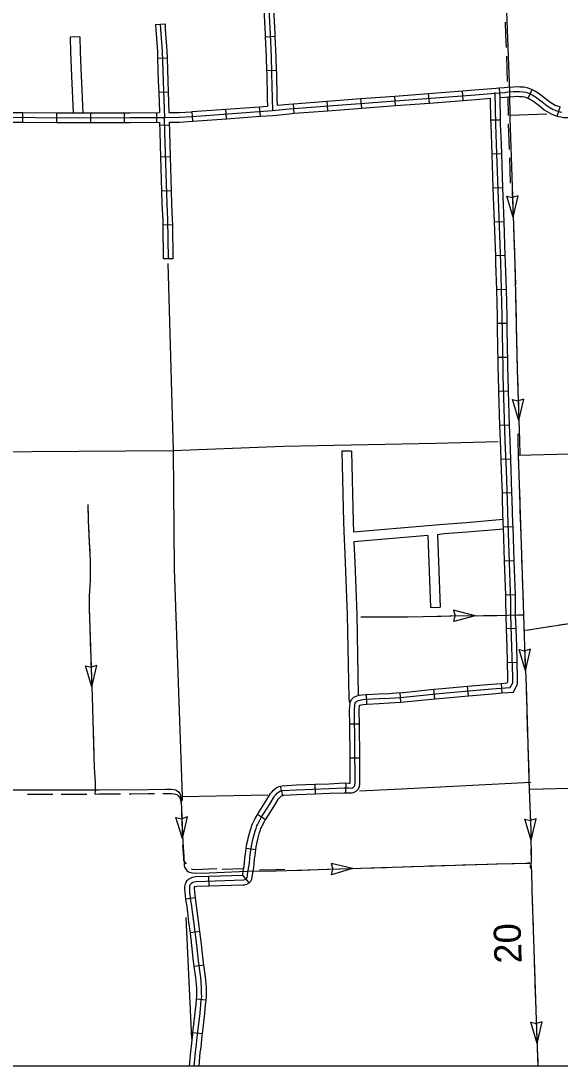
# Model space of a CAD drawing. Extents: x 1164457 to 1439835, y 1590918 to 1773502.
# Drawn here: x 1322808 to 1331207, y 1614471 to 1630737 of the extents above; entities that cross this region are included whole.
import ezdxf

# ---------------------------------------------------------------- set-up
doc = ezdxf.new("R2010")
doc.units = 0
for name, color, linetype in [('Level 32', 7, 'Continuous'), ('Level 43', 7, 'Continuous'), ('Level 46', 7, 'Continuous'), ('Level 5', 7, 'Continuous'), ('R_Draft', 7, 'Continuous')]:
    doc.layers.add(name, color=color, linetype=linetype)

msp = doc.modelspace()

# ---------------------------------------------------------------- linework, layer by layer
at = {"layer": 'Level 32'}
for p, q in [((1324905, 1630683), (1325055, 1630689)), ((1326615, 1630490), (1326765, 1630497)), ((1324938, 1630157), (1325088, 1630162)), ((1326636, 1629964), (1326786, 1629968)), ((1324955, 1629629), (1325104, 1629634)), ((1328644, 1629419), (1328633, 1629568)), ((1329171, 1629459), (1329159, 1629609)), ((1329697, 1629499), (1329686, 1629649)), ((1330272, 1629544), (1330261, 1629693)), ((1330708, 1629534), (1330771, 1629670)), ((1326539, 1629253), (1326527, 1629402)), ((1327065, 1629299), (1327053, 1629448)), ((1327591, 1629339), (1327580, 1629488)), ((1328118, 1629379), (1328106, 1629528)), ((1331164, 1629256), (1331207, 1629400)), ((1322840, 1629160), (1322841, 1629310)), ((1323368, 1629157), (1323369, 1629307)), ((1323896, 1629156), (1323896, 1629306)), ((1324424, 1629157), (1324424, 1629307)), ((1324927, 1629159), (1324926, 1629309)), ((1325485, 1629175), (1325474, 1629325)), ((1326012, 1629214), (1326001, 1629363)), ((1325123, 1629114), (1324974, 1629107)), ((1330280, 1629194), (1330130, 1629191)), ((1325140, 1628619), (1324990, 1628614)), ((1330298, 1628668), (1330148, 1628662)), ((1325155, 1628091), (1325005, 1628087)), ((1330316, 1628140), (1330166, 1628135)), ((1330335, 1627612), (1330185, 1627607)), ((1325173, 1627562), (1325023, 1627560)), ((1325181, 1627034), (1325031, 1627032)), ((1330354, 1627085), (1330204, 1627079)), ((1330370, 1626556), (1330220, 1626552)), ((1330384, 1626027), (1330234, 1626026)), ((1330391, 1625500), (1330241, 1625497)), ((1330404, 1624973), (1330254, 1624968)), ((1330420, 1624445), (1330270, 1624441)), ((1330438, 1623918), (1330288, 1623912)), ((1330458, 1623390), (1330308, 1623385)), ((1330475, 1622862), (1330325, 1622857)), ((1330492, 1622335), (1330342, 1622330)), ((1330510, 1621807), (1330360, 1621802)), ((1330523, 1621280), (1330373, 1621274)), ((1330539, 1620751), (1330389, 1620747)), ((1328727, 1620133), (1328718, 1620283)), ((1329255, 1620186), (1329240, 1620336)), ((1329780, 1620233), (1329767, 1620383)), ((1330306, 1620278), (1330294, 1620427)), ((1328199, 1620105), (1328192, 1620255)), ((1328081, 1619792), (1327931, 1619791)), ((1328086, 1619264), (1327936, 1619263)), ((1326886, 1618683), (1326853, 1618829)), ((1327399, 1618708), (1327394, 1618858)), ((1327868, 1618726), (1327875, 1618876)), ((1326619, 1618304), (1326492, 1618384)), ((1326467, 1617835), (1326318, 1617857)), ((1325739, 1617276), (1325735, 1617426)), ((1326363, 1617322), (1326263, 1617442)), ((1325529, 1617087), (1325380, 1617068)), ((1325596, 1616563), (1325448, 1616544)), ((1325658, 1616040), (1325510, 1616019)), ((1325694, 1615497), (1325545, 1615511)), ((1325636, 1614971), (1325487, 1614988))]:
    msp.add_line(p, q, dxfattribs=at)
for points in [[(1326680, 1632040), (1326659, 1632033), (1326642, 1632021), (1326631, 1632008), (1326618, 1631991), (1326611, 1631974), (1326606, 1631955), (1326603, 1631927), (1326605, 1631875), (1326612, 1631805), (1326623, 1631721), (1326639, 1631515), (1326689, 1630530), (1326705, 1630176), (1326713, 1629923), (1326721, 1629528), (1326728, 1629342)], [(1326589, 1631017), (1326614, 1630526), (1326615, 1630490)], [(1326739, 1631025), (1326763, 1630534), (1326765, 1630497)], [(1324905, 1630683), (1324908, 1630599), (1324935, 1630263), (1324938, 1630157)], [(1324980, 1630686), (1324983, 1630604), (1325010, 1630267), (1325024, 1629795), (1325043, 1629234)], [(1325055, 1630689), (1325058, 1630608), (1325084, 1630271), (1325088, 1630162)], [(1326615, 1630490), (1326630, 1630173), (1326636, 1629964)], [(1326765, 1630497), (1326780, 1630179), (1326786, 1629968)], [(1324938, 1630157), (1324949, 1629793), (1324955, 1629629)], [(1325088, 1630162), (1325099, 1629798), (1325104, 1629634)], [(1326636, 1629964), (1326638, 1629921), (1326646, 1629526), (1326650, 1629411)], [(1326786, 1629968), (1326788, 1629925), (1326796, 1629530), (1326800, 1629425)], [(1330212, 1629689), (1330252, 1629693), (1330337, 1629699), (1330384, 1629705), (1330479, 1629712), (1330542, 1629714), (1330581, 1629712), (1330640, 1629709), (1330690, 1629698), (1330746, 1629682), (1330771, 1629670)], [(1324955, 1629629), (1324965, 1629309)], [(1325043, 1629234), (1325275, 1629237), (1325477, 1629250), (1326728, 1629342), (1326987, 1629368), (1329882, 1629588), (1330258, 1629618), (1330345, 1629624), (1330392, 1629631), (1330483, 1629637), (1330541, 1629639), (1330577, 1629637), (1330630, 1629635), (1330672, 1629626), (1330720, 1629611), (1330770, 1629588), (1330826, 1629556), (1330926, 1629478), (1331004, 1629414), (1331099, 1629357), (1331157, 1629337), (1331203, 1629323), (1331234, 1629316)], [(1325104, 1629634), (1325115, 1629310)], [(1328106, 1629528), (1328633, 1629568)], [(1328633, 1629568), (1329159, 1629609)], [(1329159, 1629609), (1329686, 1629649)], [(1329686, 1629649), (1329876, 1629663), (1330212, 1629689)], [(1330387, 1623280), (1330370, 1623742), (1330352, 1624204), (1330321, 1625212), (1330319, 1625333), (1330314, 1625594), (1330307, 1626141), (1330283, 1626971), (1330217, 1628819), (1330206, 1629129), (1330196, 1629622)], [(1330272, 1629544), (1330353, 1629550), (1330400, 1629556), (1330487, 1629562), (1330540, 1629564), (1330573, 1629562), (1330620, 1629560), (1330653, 1629553), (1330693, 1629541), (1330708, 1629534)], [(1330280, 1629194), (1330272, 1629544)], [(1330771, 1629670), (1330805, 1629655), (1330868, 1629618), (1330973, 1629536), (1331047, 1629476), (1331131, 1629426), (1331180, 1629408), (1331207, 1629400)], [(1326001, 1629363), (1326527, 1629402)], [(1326527, 1629402), (1326650, 1629411)], [(1326800, 1629425), (1326981, 1629443), (1327053, 1629448)], [(1327053, 1629448), (1327580, 1629488)], [(1327580, 1629488), (1328106, 1629528)], [(1327591, 1629339), (1328118, 1629379)], [(1328118, 1629379), (1328644, 1629419)], [(1328644, 1629419), (1329171, 1629459)], [(1329171, 1629459), (1329697, 1629499)], [(1329697, 1629499), (1329887, 1629513), (1330123, 1629532)], [(1330130, 1629191), (1330123, 1629532)], [(1330708, 1629534), (1330736, 1629521), (1330784, 1629493), (1330879, 1629419), (1330961, 1629352), (1331067, 1629289), (1331133, 1629266), (1331164, 1629256)], [(1319672, 1629234), (1321015, 1629234), (1322362, 1629237), (1323701, 1629231), (1324513, 1629232), (1325043, 1629234)], [(1322312, 1629312), (1322362, 1629312), (1322841, 1629310)], [(1322841, 1629310), (1323369, 1629307)], [(1323369, 1629307), (1323701, 1629306), (1323896, 1629306)], [(1323896, 1629306), (1324424, 1629307)], [(1324424, 1629307), (1324512, 1629307), (1324965, 1629309)], [(1325106, 1627033), (1325097, 1627644), (1325086, 1627886), (1325053, 1629006), (1325043, 1629234)], [(1325115, 1629310), (1325272, 1629312), (1325472, 1629324), (1325474, 1629325)], [(1325474, 1629325), (1326001, 1629363)], [(1326012, 1629214), (1326539, 1629253)], [(1326539, 1629253), (1326734, 1629267), (1326994, 1629293), (1327065, 1629299)], [(1327065, 1629299), (1327591, 1629339)], [(1331164, 1629256), (1331184, 1629250), (1331221, 1629242), (1331262, 1629236), (1331322, 1629235), (1331469, 1629237), (1331697, 1629237), (1331714, 1629238)], [(1322312, 1629162), (1322362, 1629162), (1322840, 1629160)], [(1322840, 1629160), (1323368, 1629157)], [(1323368, 1629157), (1323701, 1629156), (1323896, 1629156)], [(1323896, 1629156), (1324424, 1629157)], [(1324424, 1629157), (1324513, 1629157), (1324971, 1629159)], [(1324990, 1628614), (1324978, 1629003), (1324971, 1629159)], [(1325121, 1629160), (1325278, 1629162), (1325482, 1629175), (1325485, 1629175)], [(1325140, 1628619), (1325128, 1629009), (1325121, 1629160)], [(1325485, 1629175), (1326012, 1629214)], [(1330148, 1628662), (1330142, 1628816), (1330131, 1629127), (1330130, 1629191)], [(1330298, 1628668), (1330292, 1628821), (1330281, 1629131), (1330280, 1629194)], [(1325005, 1628087), (1324990, 1628614)], [(1325155, 1628091), (1325140, 1628619)], [(1330166, 1628135), (1330148, 1628662)], [(1330316, 1628140), (1330298, 1628668)], [(1325023, 1627560), (1325022, 1627642), (1325011, 1627883), (1325005, 1628087)], [(1325173, 1627562), (1325172, 1627646), (1325161, 1627889), (1325155, 1628091)], [(1330185, 1627607), (1330166, 1628135)], [(1330335, 1627612), (1330316, 1628140)], [(1330204, 1627079), (1330185, 1627607)], [(1330354, 1627085), (1330335, 1627612)], [(1325031, 1627032), (1325023, 1627560)], [(1325181, 1627034), (1325173, 1627562)], [(1330220, 1626552), (1330208, 1626968), (1330204, 1627079)], [(1330370, 1626556), (1330358, 1626973), (1330354, 1627085)], [(1330234, 1626026), (1330232, 1626139), (1330220, 1626552)], [(1330384, 1626027), (1330382, 1626142), (1330370, 1626556)], [(1330241, 1625497), (1330239, 1625593), (1330234, 1626026)], [(1330391, 1625500), (1330389, 1625595), (1330384, 1626027)], [(1330254, 1624968), (1330246, 1625211), (1330244, 1625332), (1330241, 1625497)], [(1330404, 1624973), (1330396, 1625214), (1330394, 1625335), (1330391, 1625500)], [(1330270, 1624441), (1330254, 1624968)], [(1330420, 1624445), (1330404, 1624973)], [(1330288, 1623912), (1330277, 1624201), (1330270, 1624441)], [(1330438, 1623918), (1330427, 1624206), (1330420, 1624445)], [(1330308, 1623385), (1330295, 1623739), (1330288, 1623912)], [(1330458, 1623390), (1330445, 1623745), (1330438, 1623918)], [(1330325, 1622857), (1330323, 1622913), (1330312, 1623278), (1330308, 1623385)], [(1330475, 1622862), (1330473, 1622918), (1330462, 1623283), (1330458, 1623390)], [(1330470, 1620436), (1330469, 1620526), (1330458, 1620997), (1330440, 1621491), (1330438, 1621702), (1330398, 1622915), (1330387, 1623280)], [(1330342, 1622330), (1330325, 1622857)], [(1330492, 1622335), (1330475, 1622862)], [(1330360, 1621802), (1330342, 1622330)], [(1330510, 1621807), (1330492, 1622335)], [(1330373, 1621274), (1330365, 1621489), (1330363, 1621701), (1330360, 1621802)], [(1330523, 1621280), (1330515, 1621493), (1330513, 1621704), (1330510, 1621807)], [(1330389, 1620747), (1330383, 1620995), (1330373, 1621274)], [(1330539, 1620751), (1330533, 1621000), (1330523, 1621280)], [(1330294, 1620427), (1330385, 1620434), (1330395, 1620454), (1330394, 1620525), (1330389, 1620747)], [(1330306, 1620278), (1330479, 1620291), (1330545, 1620418), (1330544, 1620528), (1330539, 1620751)], [(1328183, 1620180), (1328387, 1620190), (1328545, 1620198), (1328723, 1620208), (1329375, 1620274), (1330146, 1620340), (1330432, 1620363), (1330470, 1620436)], [(1328192, 1620255), (1328384, 1620265), (1328541, 1620272), (1328718, 1620283)], [(1328717, 1620282), (1329240, 1620336)], [(1329240, 1620336), (1329368, 1620348), (1329767, 1620383)], [(1329767, 1620383), (1330140, 1620415), (1330294, 1620427)], [(1329780, 1620233), (1330153, 1620265), (1330306, 1620278)], [(1325509, 1614471), (1325529, 1614690), (1325539, 1614770), (1325559, 1614960), (1325599, 1615298), (1325612, 1615425), (1325619, 1615505), (1325625, 1615551), (1325623, 1615616), (1325622, 1615693), (1325609, 1615852), (1325573, 1616110), (1325547, 1616357), (1325500, 1616720), (1325481, 1616877), (1325465, 1616997), (1325458, 1617044), (1325442, 1617177), (1325438, 1617237), (1325438, 1617261), (1325442, 1617285), (1325448, 1617299), (1325455, 1617309), (1325465, 1617318), (1325486, 1617331), (1325505, 1617339), (1325540, 1617345), (1326280, 1617367), (1326298, 1617373), (1326316, 1617382), (1326327, 1617394), (1326333, 1617406), (1326337, 1617426), (1326340, 1617458), (1326361, 1617571), (1326367, 1617631), (1326372, 1617700), (1326381, 1617765), (1326399, 1617895), (1326414, 1617971), (1326425, 1618020), (1326455, 1618127), (1326471, 1618171), (1326477, 1618190), (1326484, 1618211), (1326497, 1618238), (1326523, 1618290), (1326551, 1618338), (1326689, 1618555), (1326760, 1618671), (1326774, 1618688), (1326798, 1618716), (1326825, 1618738), (1326853, 1618753), (1326886, 1618760), (1327103, 1618771), (1327611, 1618791), (1327846, 1618802), (1327921, 1618799), (1327957, 1618797), (1327973, 1618803), (1327989, 1618810), (1328001, 1618822), (1328010, 1618841), (1328014, 1618867), (1328014, 1618902), (1328004, 1620006), (1328010, 1620102), (1328014, 1620119), (1328023, 1620134), (1328038, 1620147), (1328066, 1620161), (1328091, 1620168), (1328135, 1620175), (1328183, 1620180)], [(1327931, 1619791), (1327929, 1620008), (1327935, 1620115), (1327945, 1620147), (1327963, 1620182), (1327997, 1620210), (1328039, 1620231), (1328075, 1620241), (1328125, 1620249), (1328178, 1620255), (1328192, 1620255)], [(1328199, 1620105), (1328391, 1620115), (1328549, 1620123), (1328727, 1620133)], [(1328727, 1620133), (1328729, 1620133), (1329255, 1620186)], [(1329255, 1620186), (1329382, 1620199), (1329780, 1620233)], [(1328081, 1619792), (1328079, 1620004), (1328084, 1620086), (1328093, 1620090), (1328107, 1620094), (1328144, 1620100), (1328189, 1620105), (1328199, 1620105)], [(1327936, 1619263), (1327931, 1619791)], [(1328086, 1619264), (1328081, 1619792)], [(1327921, 1618724), (1327967, 1618722), (1328001, 1618733), (1328032, 1618748), (1328063, 1618778), (1328083, 1618819), (1328089, 1618861), (1328089, 1618902), (1328086, 1619264)], [(1327927, 1618874), (1327939, 1618873), (1327939, 1618902), (1327936, 1619263)], [(1326492, 1618384), (1326625, 1618595), (1326698, 1618713), (1326715, 1618735), (1326746, 1618771), (1326785, 1618801), (1326827, 1618824), (1326853, 1618829)], [(1326853, 1618829), (1326876, 1618835), (1327099, 1618846), (1327394, 1618858)], [(1327394, 1618858), (1327608, 1618866), (1327846, 1618877), (1327924, 1618874), (1327927, 1618874)], [(1326619, 1618304), (1326752, 1618515), (1326822, 1618628), (1326832, 1618641), (1326850, 1618662), (1326866, 1618675), (1326880, 1618682), (1326886, 1618683)], [(1326886, 1618683), (1326897, 1618685), (1327106, 1618696), (1327399, 1618708)], [(1327399, 1618708), (1327614, 1618716), (1327846, 1618726), (1327918, 1618724), (1327921, 1618724)], [(1326318, 1617857), (1326325, 1617907), (1326341, 1617986), (1326352, 1618038), (1326383, 1618150), (1326400, 1618196), (1326406, 1618215), (1326415, 1618240), (1326430, 1618271), (1326457, 1618326), (1326487, 1618377), (1326492, 1618384)], [(1326467, 1617835), (1326473, 1617882), (1326487, 1617956), (1326498, 1618002), (1326526, 1618104), (1326542, 1618147), (1326548, 1618166), (1326554, 1618182), (1326565, 1618205), (1326589, 1618254), (1326615, 1618299), (1326619, 1618304)], [(1326263, 1617442), (1326263, 1617442), (1326266, 1617469), (1326287, 1617582), (1326293, 1617638), (1326298, 1617707), (1326307, 1617776), (1326318, 1617857)], [(1326267, 1617292), (1326292, 1617293), (1326326, 1617303), (1326363, 1617322), (1326388, 1617351), (1326405, 1617381), (1326411, 1617416), (1326414, 1617447), (1326435, 1617560), (1326442, 1617625), (1326447, 1617692), (1326455, 1617755), (1326467, 1617835)], [(1325380, 1617068), (1325367, 1617170), (1325362, 1617234), (1325363, 1617267), (1325370, 1617307), (1325382, 1617335), (1325398, 1617359), (1325419, 1617378), (1325451, 1617398), (1325484, 1617412), (1325532, 1617420), (1325735, 1617426)], [(1325735, 1617426), (1326263, 1617442)], [(1325529, 1617087), (1325517, 1617185), (1325513, 1617239), (1325513, 1617254), (1325514, 1617260), (1325520, 1617264), (1325526, 1617267), (1325547, 1617270), (1325739, 1617276)], [(1325739, 1617276), (1326267, 1617292)], [(1325448, 1616544), (1325426, 1616711), (1325407, 1616867), (1325391, 1616987), (1325384, 1617034), (1325380, 1617068)], [(1325596, 1616563), (1325575, 1616730), (1325556, 1616886), (1325540, 1617008), (1325533, 1617055), (1325529, 1617087)], [(1325510, 1616019), (1325498, 1616101), (1325473, 1616349), (1325448, 1616544)], [(1325658, 1616040), (1325647, 1616119), (1325622, 1616366), (1325596, 1616563)], [(1325545, 1615511), (1325545, 1615513), (1325550, 1615555), (1325548, 1615615), (1325547, 1615689), (1325534, 1615843), (1325510, 1616019)], [(1325694, 1615496), (1325700, 1615548), (1325698, 1615618), (1325697, 1615696), (1325683, 1615860), (1325658, 1616040)], [(1325487, 1614988), (1325524, 1615306), (1325537, 1615433), (1325545, 1615511)], [(1325636, 1614971), (1325674, 1615290), (1325686, 1615418), (1325694, 1615497)], [(1325434, 1614471), (1325454, 1614698), (1325465, 1614779), (1325485, 1614969), (1325487, 1614988)], [(1325585, 1614471), (1325603, 1614682), (1325614, 1614762), (1325634, 1614952), (1325636, 1614971)]]:
    msp.add_lwpolyline(points, dxfattribs=at)
at = {"layer": 'Level 43'}
for p, q in [((1330477, 1627683), (1330377, 1628011)), ((1330377, 1628011), (1330466, 1627990)), ((1330555, 1628017), (1330467, 1627990)), ((1330477, 1627683), (1330555, 1628017)), ((1330564, 1624516), (1330465, 1624844)), ((1330465, 1624844), (1330554, 1624824)), ((1330642, 1624850), (1330555, 1624824)), ((1330564, 1624516), (1330642, 1624850)), ((1330667, 1620623), (1330569, 1620952)), ((1330569, 1620952), (1330658, 1620931)), ((1330746, 1620957), (1330659, 1620931)), ((1330667, 1620623), (1330746, 1620957)), ((1323913, 1620373), (1323813, 1620701)), ((1323813, 1620701), (1323902, 1620681)), ((1323991, 1620707), (1323903, 1620681)), ((1323913, 1620373), (1323991, 1620707)), ((1325326, 1618013), (1325224, 1618340)), ((1325224, 1618340), (1325313, 1618320)), ((1325401, 1618348), (1325314, 1618320)), ((1325326, 1618013), (1325401, 1618348)), ((1330834, 1618320), (1330746, 1618292)), ((1330758, 1617985), (1330834, 1618320)), ((1330758, 1617985), (1330656, 1618313)), ((1330656, 1618313), (1330745, 1618292)), ((1327974, 1617547), (1327640, 1617625)), ((1327640, 1617625), (1327666, 1617537)), ((1327974, 1617547), (1327646, 1617447)), ((1327646, 1617447), (1327666, 1617536)), ((1330849, 1614824), (1330749, 1615153)), ((1330749, 1615152), (1330838, 1615132)), ((1330926, 1615159), (1330839, 1615132)), ((1330849, 1614824), (1330927, 1615159))]:
    msp.add_line(p, q, dxfattribs=at)
for points in [[(1331528, 1637605), (1330434, 1636452), (1330294, 1636286), (1330272, 1636249), (1330252, 1636222), (1330232, 1636178), (1330218, 1636126), (1330206, 1636072), (1330199, 1636026), (1330189, 1635859), (1330225, 1635001), (1330231, 1634903), (1330320, 1632272), (1330417, 1629632), (1330424, 1629223), (1330503, 1626944), (1330539, 1625302), (1330574, 1624205), (1330581, 1623987)], [(1330350, 1630717), (1330357, 1630519)], [(1330357, 1630519), (1330365, 1630321)], [(1330370, 1630189), (1330384, 1629794)], [(1330391, 1629556), (1330396, 1629266)], [(1330400, 1629134), (1330413, 1628738)], [(1330418, 1628606), (1330432, 1628210)], [(1330463, 1628078), (1330477, 1627683)], [(1330482, 1627551), (1330489, 1627353)], [(1330489, 1627353), (1330496, 1627155)], [(1330500, 1627023), (1330503, 1626944), (1330510, 1626627)], [(1330513, 1626495), (1330522, 1626099)], [(1330525, 1625967), (1330533, 1625571)], [(1330536, 1625440), (1330539, 1625302), (1330547, 1625044)], [(1330552, 1624912), (1330564, 1624516)], [(1330547, 1624313), (1330547, 1624205), (1330547, 1624186)], [(1330547, 1624186), (1330553, 1623988)], [(1330554, 1623987), (1330637, 1621495), (1330652, 1621000), (1330677, 1620390), (1330721, 1618934), (1330727, 1618777), (1330751, 1618145), (1330754, 1617638), (1330749, 1617617), (1330744, 1617596), (1330738, 1617575), (1330748, 1617557), (1330754, 1617542), (1330760, 1617508), (1330769, 1617202), (1330801, 1616136), (1330842, 1615030), (1330860, 1614471)], [(1330554, 1623987), (1330560, 1623789)], [(1330565, 1623657), (1330578, 1623262)], [(1323849, 1623209), (1323855, 1622957), (1323873, 1622623), (1323888, 1622336), (1323885, 1622029), (1323870, 1621779), (1323871, 1621596), (1323918, 1620216), (1323952, 1619115), (1323964, 1618891), (1323964, 1618771), (1323961, 1618703)], [(1323849, 1623209), (1323854, 1623011)], [(1330582, 1623130), (1330596, 1622734)], [(1323859, 1622879), (1323873, 1622623), (1323880, 1622484)], [(1330600, 1622602), (1330613, 1622206)], [(1323887, 1622352), (1323888, 1622336), (1323885, 1622029), (1323881, 1621956)], [(1330618, 1622074), (1330631, 1621679)], [(1323873, 1621824), (1323870, 1621779), (1323871, 1621596), (1323877, 1621428)], [(1328102, 1621465), (1328319, 1621461), (1328711, 1621461), (1329076, 1621467), (1329292, 1621471), (1329509, 1621477), (1329761, 1621483), (1329919, 1621476), (1330019, 1621483), (1330222, 1621485), (1330558, 1621492), (1330637, 1621495)], [(1328102, 1621465), (1328300, 1621461)], [(1328432, 1621461), (1328711, 1621461), (1328828, 1621463)], [(1328960, 1621465), (1329076, 1621467), (1329292, 1621471), (1329356, 1621473)], [(1329488, 1621477), (1329509, 1621477), (1329761, 1621483), (1329884, 1621478)], [(1329884, 1621478), (1329545, 1621566), (1329572, 1621479)], [(1329884, 1621478), (1329552, 1621390), (1329572, 1621479)], [(1330016, 1621483), (1330019, 1621483), (1330222, 1621485), (1330365, 1621488)], [(1330544, 1621491), (1330558, 1621492), (1330637, 1621495)], [(1330635, 1621547), (1330637, 1621495), (1330647, 1621151)], [(1323882, 1621297), (1323895, 1620901)], [(1331385, 1621361), (1331175, 1621327), (1330878, 1621282), (1330747, 1621259), (1330716, 1621256), (1330644, 1621248)], [(1331068, 1621311), (1330878, 1621282), (1330747, 1621259), (1330716, 1621256), (1330644, 1621248)], [(1331394, 1621363), (1331385, 1621361), (1331199, 1621331)], [(1330651, 1621019), (1330652, 1621000), (1330659, 1620821)], [(1323900, 1620769), (1323913, 1620373)], [(1330659, 1620821), (1330667, 1620623)], [(1330673, 1620491), (1330677, 1620390), (1330686, 1620096)], [(1323918, 1620241), (1323918, 1620216), (1323924, 1620043)], [(1323924, 1620043), (1323930, 1619845)], [(1330690, 1619964), (1330702, 1619568)], [(1323934, 1619713), (1323946, 1619318)], [(1330706, 1619436), (1330718, 1619040)], [(1323950, 1619186), (1323952, 1619115), (1323964, 1618891), (1323964, 1618790)], [(1330722, 1618908), (1330727, 1618777), (1330737, 1618512)], [(1336751, 1618936), (1335937, 1618919), (1335726, 1618910), (1333666, 1618850), (1333653, 1618851), (1333601, 1618842), (1333530, 1618843), (1333363, 1618838), (1332619, 1618821), (1330727, 1618777)], [(1319939, 1618746), (1320065, 1618751), (1320194, 1618756), (1320458, 1618759), (1321089, 1618764), (1321346, 1618755), (1321817, 1618769), (1323961, 1618768), (1324024, 1618771), (1324392, 1618774), (1324529, 1618772), (1324797, 1618777)], [(1322909, 1618703), (1323107, 1618703)], [(1323107, 1618703), (1323305, 1618703)], [(1323437, 1618703), (1323833, 1618703)], [(1323965, 1618703), (1324024, 1618706), (1324361, 1618709)], [(1324493, 1618707), (1324529, 1618707), (1324797, 1618712), (1324889, 1618712)], [(1324797, 1618777), (1325064, 1618778), (1325151, 1618778), (1325197, 1618775), (1325219, 1618769), (1325237, 1618761), (1325269, 1618732), (1325282, 1618713), (1325295, 1618683), (1325302, 1618647), (1325305, 1618594), (1325320, 1618211), (1325330, 1617960), (1325349, 1617734), (1325349, 1617708), (1325354, 1617632), (1325354, 1617593), (1325356, 1617566), (1325380, 1617535), (1325393, 1617514), (1325421, 1617495), (1325459, 1617483), (1325484, 1617477), (1325524, 1617473), (1325743, 1617480), (1326335, 1617503), (1326784, 1617508), (1330234, 1617620), (1330671, 1617629), (1330738, 1617640)], [(1325021, 1618713), (1325064, 1618713), (1325151, 1618713), (1325197, 1618710), (1325219, 1618704), (1325237, 1618696), (1325269, 1618667), (1325282, 1618648), (1325295, 1618618), (1325302, 1618582), (1325304, 1618540)], [(1331144, 1618786), (1330748, 1618777)], [(1325310, 1618408), (1325320, 1618146), (1325326, 1618013)], [(1330742, 1618381), (1330751, 1618145), (1330752, 1617985)], [(1325326, 1617908), (1325342, 1617711)], [(1330753, 1617853), (1330754, 1617655)], [(1325341, 1617726), (1325342, 1617711), (1325342, 1617686), (1325343, 1617670), (1325385, 1617621)], [(1325462, 1617541), (1325479, 1617537), (1325518, 1617532), (1325737, 1617540), (1325858, 1617545)], [(1325941, 1617533), (1326283, 1617547)], [(1326523, 1617527), (1326784, 1617530), (1326919, 1617534)], [(1327050, 1617517), (1327446, 1617530)], [(1327578, 1617534), (1327974, 1617547)], [(1328106, 1617551), (1328304, 1617557)], [(1328304, 1617557), (1328502, 1617564)], [(1328634, 1617568), (1329029, 1617581)], [(1329161, 1617585), (1329557, 1617598)], [(1329689, 1617602), (1330085, 1617615)], [(1330217, 1617619), (1330234, 1617620), (1330754, 1617631)], [(1330754, 1617655), (1330754, 1617638), (1330749, 1617617), (1330754, 1617542), (1330760, 1617508), (1330761, 1617463)], [(1330765, 1617331), (1330769, 1617202), (1330777, 1616935)], [(1330781, 1616803), (1330793, 1616407)], [(1330797, 1616275), (1330801, 1616136), (1330810, 1615880)], [(1330815, 1615748), (1330830, 1615352)], [(1330835, 1615220), (1330842, 1615030), (1330849, 1614824)], [(1330853, 1614692), (1330859, 1614495)], [(1330859, 1614495), (1330860, 1614471)]]:
    msp.add_lwpolyline(points, dxfattribs=at)
at = {"layer": 'Level 46'}
for points in [[(1323727, 1630487), (1323577, 1630483), (1323583, 1630244), (1323598, 1629882), (1323623, 1629306)], [(1323727, 1630487), (1323733, 1630249), (1323748, 1629888), (1323773, 1629306)], [(1327959, 1624043), (1327809, 1624040), (1327833, 1622935), (1327843, 1622668), (1327848, 1622569), (1327859, 1622302), (1327891, 1621494), (1327914, 1620198), (1327921, 1620151), (1327933, 1620124)], [(1327959, 1624043), (1327983, 1622939), (1327989, 1622778)], [(1330321, 1622979), (1329748, 1622928), (1329391, 1622902), (1329210, 1622883), (1327989, 1622778)], [(1329147, 1622727), (1327995, 1622628)], [(1329147, 1622727), (1329187, 1621607), (1329337, 1621612)], [(1330326, 1622829), (1329760, 1622778), (1329404, 1622752), (1329297, 1622741)], [(1329297, 1622741), (1329337, 1621612)], [(1327995, 1622628), (1328009, 1622308), (1328041, 1621498), (1328064, 1620239)]]:
    msp.add_lwpolyline(points, dxfattribs=at)
at = {"layer": 'Level 5'}
for points in [[(1330426, 1629272), (1331002, 1629289)], [(1325097, 1626960), (1325178, 1624053)], [(1325178, 1624053), (1326899, 1624117), (1329271, 1624163), (1330244, 1624192)], [(1319797, 1623981), (1321202, 1624016), (1322234, 1624033), (1325178, 1624053)], [(1325178, 1624053), (1325197, 1622209), (1325319, 1618664)], [(1330554, 1623981), (1335788, 1624114)], [(1328085, 1618757), (1328731, 1618787), (1330752, 1618892)], [(1325319, 1618664), (1326653, 1618694)], [(1325319, 1618664), (1325321, 1618605)], [(1325376, 1616782), (1325464, 1614900)]]:
    msp.add_lwpolyline(points, dxfattribs=at)
at = {"layer": 'R_Draft'}
msp.add_lwpolyline([(1246398, 1678582), (1349820, 1678582), (1349820, 1614471), (1246398, 1614471)], close=True, dxfattribs=at)

# ---------------------------------------------------------------- texts
at = {"layer": 'Level 43'}
msp.add_text('20', height=422, rotation=91.7789, dxfattribs=at).set_placement((1330610, 1616073))

doc.saveas('drawing.dxf')
